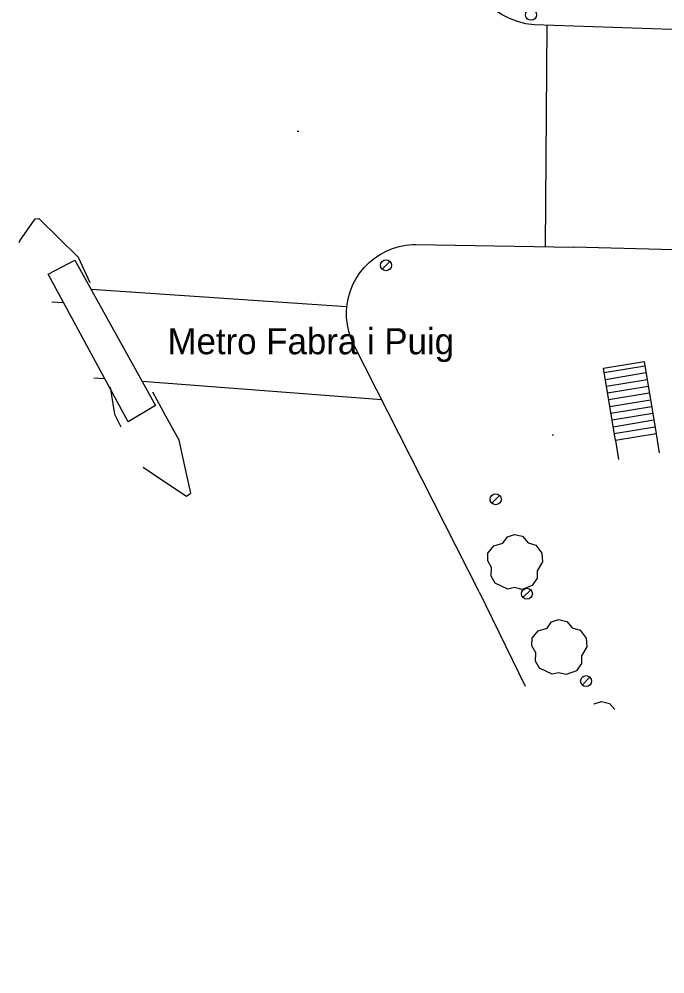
# Model space of a CAD drawing. Extents: x 431390 to 432653, y 4586754 to 4589600.
# Drawn here: x 431747.3 to 431794.4, y 4586774.7 to 4586844.3 of the extents above; entities that cross this region are included whole.
import ezdxf

# ---------------------------------------------------------------- set-up
doc = ezdxf.new("R2010")
doc.units = 0
for name, color, linetype in [('COM_16_LN', 7, 'Continuous'), ('COM_17LS_LN', 7, 'Continuous'), ('COM_51_LN', 7, 'Continuous'), ('CON_20_LN', 7, 'Continuous'), ('CON_23_LN', 7, 'Continuous'), ('ENE_06_PT', 7, 'Continuous'), ('ORO_03_PT', 7, 'Continuous'), ('TOP_17_TX', 7, 'Continuous'), ('VEG_03_PT', 7, 'Continuous')]:
    doc.layers.add(name, color=color, linetype=linetype)

msp = doc.modelspace()

# ---------------------------------------------------------------- linework, layer by layer
at = {"layer": 'COM_16_LN'}
for points in [[(431747.293, 4586828.028), (431747.337, 4586828.154), (431748.473, 4586829.755), (431748.744, 4586829.78), (431750.169, 4586828.376), (431751.593, 4586826.972), (431752.461, 4586825.116)], [(431753.929, 4586817.477), (431754.263, 4586815.505), (431754.715, 4586814.592)], [(431756.343, 4586811.643), (431757.851, 4586810.639), (431759.516, 4586809.531), (431759.832, 4586809.762), (431759.386, 4586811.712), (431758.96, 4586813.61), (431758.005, 4586815.367), (431757.05, 4586817.124)]]:
    msp.add_lwpolyline(points, dxfattribs=at)
at = {"layer": 'COM_17LS_LN'}
for points in [[(431796.36, 4586843.5), (431784.88, 4586843.889), (431784.266, 4586843.982), (431783.664, 4586844.138), (431783.082, 4586844.355), (431782.526, 4586844.631), (431782.001, 4586844.962), (431781.512, 4586845.346), (431781.066, 4586845.778), (431780.667, 4586846.254), (431780.319, 4586846.768), (431780.025, 4586847.315), (431779.79, 4586847.89), (431777, 4586908.02), (431777.16, 4586908.53), (431779.16, 4586910.16), (431781.124, 4586911.301), (431783.707, 4586912.802), (431781.939, 4586952.061), (431780.022, 4586994.644), (431779.988, 4586995.394)], [(431780.87, 4586802.55), (431771.698, 4586820.615), (431771.5, 4586821.074), (431771.349, 4586821.55), (431771.245, 4586822.039), (431771.19, 4586822.536), (431771.185, 4586823.036), (431771.229, 4586823.534), (431771.322, 4586824.025), (431771.464, 4586824.504), (431771.652, 4586824.967), (431771.885, 4586825.409), (431772.161, 4586825.826), (431772.477, 4586826.214), (431772.829, 4586826.568), (431773.215, 4586826.886), (431773.63, 4586827.163), (431774.071, 4586827.399), (431774.533, 4586827.59), (431775.012, 4586827.733), (431775.502, 4586827.829), (431776, 4586827.876), (431776.24, 4586827.881), (431787.75, 4586827.69)], [(431863.85, 4586774.704), (431865.236, 4586797.422), (431866.475, 4586817.725), (431866.575, 4586819.362), (431866.545, 4586819.991), (431866.453, 4586820.614), (431866.301, 4586821.225), (431866.089, 4586821.819), (431865.82, 4586822.388), (431865.496, 4586822.929), (431865.121, 4586823.435), (431864.699, 4586823.901), (431864.232, 4586824.324), (431863.726, 4586824.7), (431863.186, 4586825.023), (431862.616, 4586825.293), (431862.023, 4586825.505), (431861.412, 4586825.657), (431860.789, 4586825.75), (431860.16, 4586825.78), (431787.75, 4586827.69)], [(431757.25, 4586816.14), (431755.24, 4586814.95), (431749.41, 4586825.72), (431751.35, 4586826.75), (431757.25, 4586816.14)], [(431780.87, 4586802.55), (431784.225, 4586795.694)]]:
    msp.add_lwpolyline(points, dxfattribs=at)
at = {"layer": 'COM_51_LN'}
for points in [[(431785.695, 4586827.724), (431785.831, 4586843.849)], [(431771.191, 4586823.332), (431752.546, 4586824.6)], [(431749.685, 4586823.699), (431750.53, 4586823.651)], [(431753.547, 4586818.078), (431752.752, 4586818.146)], [(431773.76, 4586816.555), (431756.276, 4586817.891)]]:
    msp.add_lwpolyline(points, dxfattribs=at)
at = {"layer": 'CON_20_LN'}
for points in [[(431790.8, 4586813.59), (431791.029, 4586812.202)], [(431793.76, 4586814.079), (431793.989, 4586812.69)]]:
    msp.add_lwpolyline(points, dxfattribs=at)
at = {"layer": 'CON_23_LN'}
for points in [[(431790.8, 4586813.59), (431789.93, 4586818.86), (431792.89, 4586819.349), (431793.76, 4586814.079)], [(431792.946, 4586819.01), (431789.986, 4586818.521)], [(431793.027, 4586818.517), (431790.067, 4586818.028)], [(431793.109, 4586818.024), (431790.149, 4586817.535)], [(431793.19, 4586817.531), (431790.23, 4586817.042)], [(431793.272, 4586817.038), (431790.312, 4586816.549)], [(431793.353, 4586816.544), (431790.393, 4586816.055)], [(431793.435, 4586816.05), (431790.474, 4586815.562)], [(431793.516, 4586815.558), (431790.556, 4586815.069)], [(431793.597, 4586815.065), (431790.637, 4586814.576)], [(431793.679, 4586814.572), (431790.719, 4586814.083)], [(431793.76, 4586814.079), (431790.8, 4586813.59)]]:
    msp.add_lwpolyline(points, dxfattribs=at)
at = {"layer": 'ENE_06_PT'}
for p, q in [((431774.341, 4586826.654), (431773.775, 4586826.088)), ((431782.342, 4586809.592), (431781.776, 4586809.026)), ((431784.622, 4586802.702), (431784.056, 4586802.136)), ((431788.942, 4586796.332), (431788.376, 4586795.766))]:
    msp.add_line(p, q, dxfattribs=at)
for centre in [(431784.639, 4586844.629), (431774.058, 4586826.371), (431782.059, 4586809.309), (431784.339, 4586802.419), (431788.659, 4586796.049)]:
    msp.add_circle(centre, 0.4, dxfattribs=at)
at = {"layer": 'ORO_03_PT'}
for p, q in [((431767.59, 4586836.149), (431767.69, 4586836.149)), ((431786.19, 4586814), (431786.29, 4586814))]:
    msp.add_line(p, q, dxfattribs=at)
at = {"layer": 'VEG_03_PT'}
for points in [[(431782.957, 4586802.755), (431782.03, 4586803.19), (431781.742, 4586803.711), (431781.765, 4586804.325), (431781.483, 4586804.817), (431781.491, 4586805.38), (431781.932, 4586805.915), (431782.585, 4586806.119), (431782.92, 4586806.57), (431783.446, 4586806.74), (431784.026, 4586806.607), (431784.426, 4586806.141), (431785, 4586805.971), (431785.434, 4586805.388), (431785.483, 4586804.746), (431785.1, 4586804.099), (431785.1, 4586803.549), (431784.728, 4586803.015), (431783.989, 4586802.74), (431783.424, 4586802.868), (431782.957, 4586802.755)], [(431786.184, 4586796.551), (431785.257, 4586796.986), (431784.969, 4586797.507), (431784.992, 4586798.121), (431784.71, 4586798.613), (431784.718, 4586799.176), (431785.159, 4586799.711), (431785.812, 4586799.915), (431786.147, 4586800.366), (431786.673, 4586800.536), (431787.253, 4586800.403), (431787.653, 4586799.937), (431788.227, 4586799.767), (431788.661, 4586799.184), (431788.71, 4586798.542), (431788.327, 4586797.895), (431788.327, 4586797.345), (431787.955, 4586796.811), (431787.216, 4586796.536), (431786.651, 4586796.664), (431786.184, 4586796.551)], [(431789.245, 4586794.37), (431789.257, 4586794.386), (431789.783, 4586794.556), (431790.363, 4586794.423), (431790.748, 4586793.974)]]:
    msp.add_lwpolyline(points, dxfattribs=at)

# ---------------------------------------------------------------- texts
at = {"layer": 'TOP_17_TX'}
msp.add_text('Metro Fabra i Puig', height=1.9, dxfattribs=at).set_placement((431758.125, 4586819.881))

doc.saveas('drawing.dxf')
